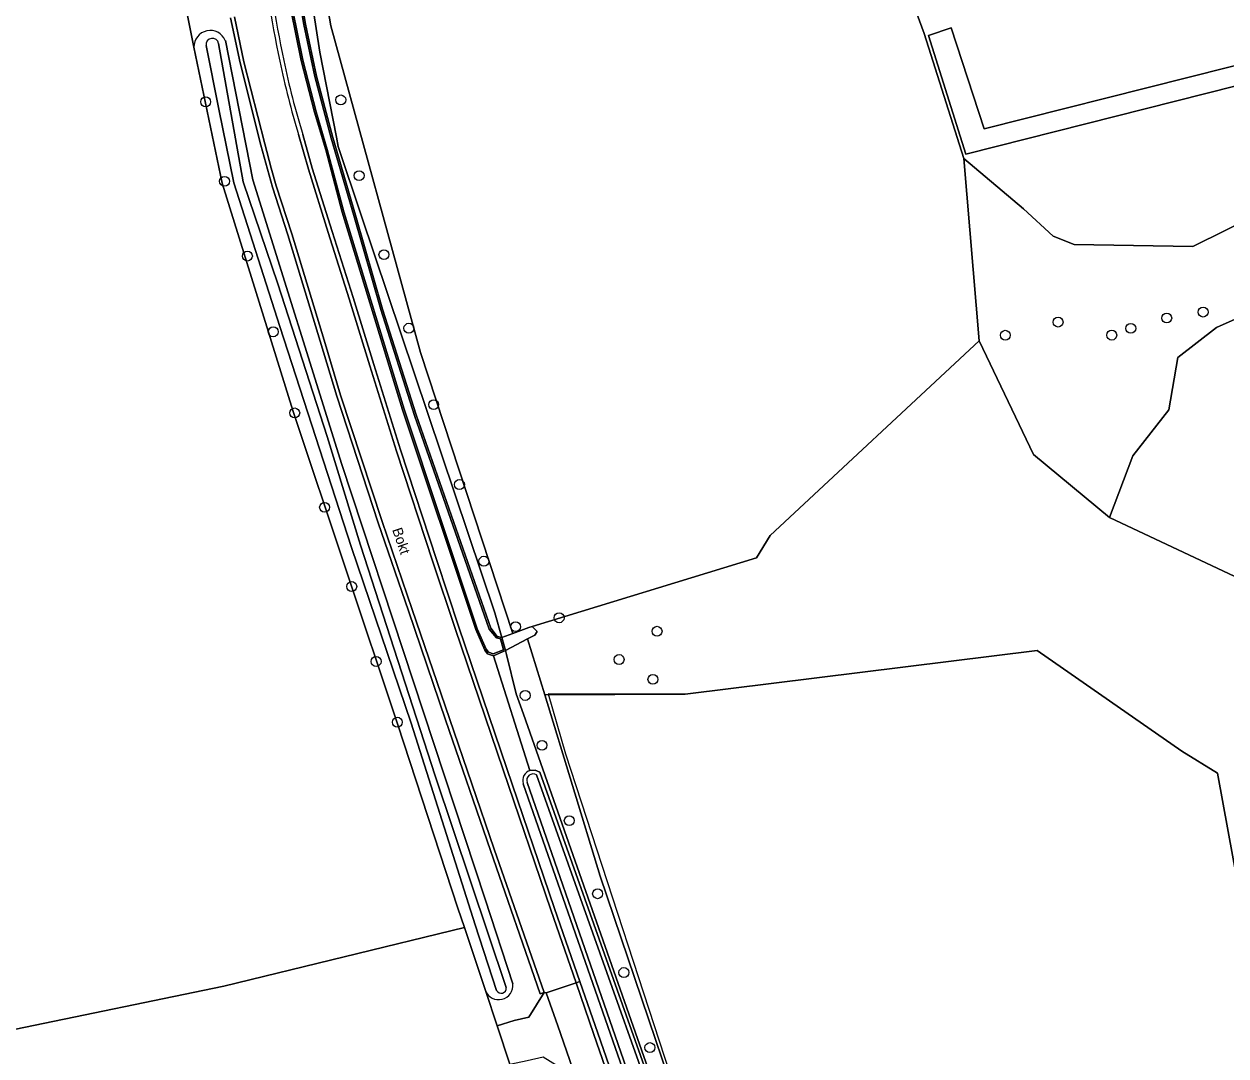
# Model space of a CAD drawing. Extents: x 162510 to 163918, y 388494 to 389774.
# Drawn here: x 163242.1 to 163360.7, y 389132.9 to 389234.8 of the extents above; entities that cross this region are included whole.
import ezdxf

# ---------------------------------------------------------------- set-up
doc = ezdxf.new("R2010")
doc.units = 0
for name, color, linetype in [('IMGEO_Boom', 7, 'Continuous'), ('IMGEO_Duiker', 7, 'Continuous'), ('IMGEO_Erf', 7, 'Continuous'), ('IMGEO_Grasland_agrarisch', 7, 'Continuous'), ('IMGEO_Grasland_overig', 7, 'Continuous'), ('IMGEO_Groenvoorziening', 7, 'Continuous'), ('IMGEO_Hek', 7, 'Continuous'), ('IMGEO_Loofbos', 7, 'Continuous'), ('IMGEO_Oever', 7, 'Continuous'), ('IMGEO_Openbare_ruimte_label', 7, 'Continuous'), ('IMGEO_Rijbaan_lokaal_gesloten', 7, 'Continuous'), ('IMGEO_Rijbaan_lokaal_halfverhard', 7, 'Continuous'), ('IMGEO_Rijbaan_lokaal_open', 7, 'Continuous'), ('IMGEO_Waterloop', 7, 'Continuous')]:
    doc.layers.add(name, color=color, linetype=linetype)

msp = doc.modelspace()

# ---------------------------------------------------------------- linework, layer by layer
at = {"layer": 'IMGEO_Boom'}
for centre in [(163260, 389227.15), (163273.34, 389227.34), (163261.86, 389219.3), (163275.15, 389219.86), (163277.6, 389212.06), (163264.12, 389211.92), (163358.49, 389206.39), (163344.17, 389205.4), (163354.9, 389205.8), (163266.67, 389204.44), (163280.06, 389204.8), (163338.96, 389204.1), (163349.47, 389204.11), (163351.35, 389204.78), (163282.51, 389197.25), (163268.79, 389196.43), (163285.06, 389189.36), (163271.74, 389187.11), (163287.47, 389181.79), (163274.42, 389179.29), (163290.6, 389175.32), (163294.9, 389176.2), (163304.57, 389174.87), (163276.83, 389171.89), (163300.82, 389172.08), (163304.16, 389170.12), (163291.55, 389168.53), (163278.92, 389165.89), (163293.21, 389163.61), (163295.9, 389156.17), (163298.7, 389148.95), (163301.29, 389141.17), (163303.86, 389133.76)]:
    msp.add_circle(centre, 0.489, dxfattribs=at)
at = {"layer": 'IMGEO_Duiker'}
msp.add_lwpolyline([(163288.41, 389172.46), (163292.02, 389161.13)], dxfattribs=at)
at = {"layer": 'IMGEO_Erf'}
msp.add_lwpolyline([(163295.99, 389113.82), (163290.94, 389129.38), (163290.9, 389129.51), (163290.03, 389132.12), (163288.77, 389135.91), (163287.62, 389139.39), (163285.54, 389145.63), (163261.78, 389139.83), (163241.1, 389135.56), (163217.2, 389130.56), (163224.26, 389085.9), (163224.4, 389084.98), (163231.97, 389086.77), (163247.9, 389090.8), (163281.65, 389099.34), (163299.1, 389104.33), (163298.18, 389106.71), (163299.75, 389107.17), (163299.51, 389107.92), (163299.36, 389108.41), (163297.84, 389113.03)], dxfattribs=at)
at = {"layer": 'IMGEO_Grasland_agrarisch'}
for points in [[(163388.88, 389260.58), (163349.51, 389250), (163329.29, 389244.57), (163327.23, 389244.02), (163330.95, 389233.91), (163334.85, 389221.56), (163340.75, 389216.59), (163343.69, 389213.89), (163345.77, 389213.07), (163357.46, 389212.88), (163363.99, 389216.09)], [(163241.1, 389135.56), (163261.78, 389139.83), (163285.54, 389145.63), (163284.91, 389147.53), (163278.98, 389165.63), (163268.64, 389196.56), (163261.63, 389219.11), (163258.84, 389232.54), (163257.29, 389240.35), (163255.91, 389250.62), (163255.18, 389257.46), (163254.95, 389259.65), (163234.72, 389258.87)], [(163446.97, 389250.33), (163429.34, 389245.86), (163417.88, 389242.96), (163335.07, 389221.97), (163331.37, 389233.7), (163333.61, 389234.45), (163336.86, 389224.47), (163417.3, 389244.79), (163428.76, 389247.68), (163436.64, 389249.67), (163454.78, 389254.26)], [(163367.57, 389208.33), (163359.8, 389204.88), (163355.99, 389201.92), (163355.12, 389196.75), (163351.55, 389192.19), (163349.24, 389186.12), (163364.42, 389178.96)]]:
    msp.add_lwpolyline(points, dxfattribs=at)
for points in [[(163290.32, 389174.65), (163291.92, 389175.23), (163292.25, 389175.35), (163314.39, 389182.12), (163315.73, 389184.32), (163336.37, 389203.54), (163334.85, 389221.56), (163330.95, 389233.91), (163327.23, 389244.02), (163327.18, 389244), (163326.31, 389243.96), (163324.51, 389250), (163323.9, 389252.04), (163322.98, 389255.13), (163320.23, 389256.1), (163270.63, 389254.09), (163271.19, 389241.33), (163272.35, 389234.67), (163281.2, 389202.41)], [(163307.16, 389126.5), (163310.88, 389115.86), (163314.09, 389104.33), (163316.99, 389092.13), (163318.51, 389073.31), (163367.52, 389078.3), (163374.79, 389079.28), (163366.65, 389123.96), (163359.92, 389160.85), (163356.4, 389163.04), (163342.1, 389172.97), (163307.36, 389168.67), (163293.48, 389168.59), (163298.96, 389150.69)], [(163359.92, 389160.85), (163356.4, 389163.04), (163342.1, 389172.97), (163307.36, 389168.67), (163293.81, 389168.69), (163295.53, 389162.77), (163307.35, 389126.56), (163307.16, 389126.5), (163310.88, 389115.86), (163314.09, 389104.33), (163316.99, 389092.13), (163318.51, 389073.31), (163367.52, 389078.3), (163374.79, 389079.28), (163366.65, 389123.96)]]:
    msp.add_lwpolyline(points, close=True, dxfattribs=at)
at = {"layer": 'IMGEO_Grasland_overig'}
for points in [[(163259.08, 389250.92), (163259.64, 389245.33), (163260.33, 389240.89), (163259.65, 389240.76), (163259.1, 389240.51), (163258.43, 389240.54), (163257.29, 389240.35), (163258.84, 389232.54)], [(163269.01, 389239.92), (163269.85, 389234.81), (163270.95, 389229.7), (163272.54, 389223.62), (163274.79, 389215.95), (163277.45, 389206.69), (163280.78, 389196.25), (163288.14, 389175.16), (163288.79, 389174.36), (163289.23, 389174.26), (163288.55, 389176.68), (163275.36, 389215.95), (163273.08, 389222.75), (163272.9, 389223.65), (163271.28, 389232.05), (163270.01, 389240.16)], [(163292.02, 389161.13), (163288.41, 389172.46), (163287.83, 389172.65), (163287.56, 389173), (163286.66, 389175.04), (163279.44, 389196.74), (163273.49, 389216.24), (163271.85, 389222.4), (163270.74, 389226.12), (163269.44, 389231.24), (163268.41, 389236.27)], [(163280.01, 389176.89), (163277.03, 389185.58), (163272.94, 389198.07), (163271.3, 389203.51), (163268.11, 389214.02), (163266.58, 389218.73), (163266.09, 389220.5), (163265.44, 389222.88), (163263.39, 389230.99), (163262.46, 389235.46)], [(163261.94, 389233.21), (163264.65, 389219.44), (163273.43, 389191.33), (163287.58, 389148.42), (163290.32, 389140.06)], [(163269.59, 389223.92), (163270.52, 389220.61), (163272.48, 389214.36), (163274.56, 389207.83), (163276.6, 389201.21), (163279.23, 389192.78), (163282.82, 389181.85), (163285.01, 389175.27), (163289.74, 389161.32), (163294.44, 389147.5), (163296.94, 389140.29), (163298.71, 389135.19), (163302.63, 389123.88), (163306.31, 389112.91), (163307.37, 389109.75), (163307.92, 389107.81), (163308.74, 389104.91), (163309.77, 389101.2)], [(163287.62, 389139.39), (163288.77, 389135.91), (163290.45, 389136.42), (163291.92, 389136.77), (163293.42, 389139.21), (163293.04, 389139.08), (163288.11, 389153.21), (163283.68, 389166.12), (163280.01, 389176.89)], [(163380.6, 389076.41), (163382.81, 389076.72), (163383.64, 389076.96), (163385.39, 389077.66), (163386.69, 389078.32), (163386.48, 389080.86), (163374.79, 389079.28), (163367.52, 389078.3), (163318.51, 389073.31), (163316.99, 389092.13), (163314.09, 389104.33), (163310.88, 389115.86), (163307.16, 389126.5), (163298.96, 389150.69), (163293.48, 389168.59), (163291.79, 389174.11), (163289.6, 389172.96)], [(163289.6, 389172.96), (163289.7, 389172.58), (163290.67, 389168.7), (163291.38, 389166.69), (163307.93, 389119.58), (163308.65, 389118.16), (163310.82, 389111.46), (163312.33, 389106.03), (163313.79, 389100.58), (163315.67, 389092.46), (163317.15, 389071.29), (163317.16, 389071.04), (163328.39, 389071.63), (163350.59, 389073.13), (163366.02, 389074.66), (163372.1, 389075.6), (163375.23, 389076.38), (163378.48, 389077.44), (163380.72, 389078.49), (163381.48, 389078.62), (163381.77, 389078.52), (163381.92, 389078.25), (163381.86, 389077.89)], [(163306.08, 389117.55), (163291.36, 389159.82)]]:
    msp.add_lwpolyline(points, dxfattribs=at)
msp.add_lwpolyline([(163336.37, 389203.54), (163341.73, 389192.33), (163349.24, 389186.12), (163351.55, 389192.19), (163355.12, 389196.75), (163355.99, 389201.92), (163359.8, 389204.88), (163367.57, 389208.33), (163374.84, 389208.08), (163378.41, 389205.74), (163383.96, 389207.59), (163391.85, 389211.28), (163392.71, 389214.73), (163390.37, 389218.92), (163383.1, 389221.75), (163377.8, 389223.11), (163371.51, 389220.89), (163363.99, 389216.09), (163357.46, 389212.88), (163345.77, 389213.07), (163343.69, 389213.89), (163340.75, 389216.59), (163334.85, 389221.56)], close=True, dxfattribs=at)
for centre, radius, start, end in [((163384.64, 389256.15), 119.55, 185.9996, 192.0239), ((163260.45, 389232.59), 1.61, 22.4064, 182.0203), ((163344.2, 389246.9), 78.07, 191.5701, 197.12), ((163292.34, 389160.15), 1.03, 107.8328, 198.5842), ((163288.93, 389139.89), 1.4, 201.2048, 6.7579)]:
    msp.add_arc(centre, radius, start, end, dxfattribs=at)
at = {"layer": 'IMGEO_Groenvoorziening'}
for points in [[(163288.55, 389176.68), (163289.23, 389174.26), (163290.32, 389174.65), (163281.2, 389202.41), (163272.35, 389234.67), (163271.19, 389241.33), (163270.63, 389254.09), (163269.08, 389254.14), (163268.99, 389251.22), (163269.1, 389250), (163270.01, 389240.16), (163271.28, 389232.05), (163272.9, 389223.65), (163273.08, 389222.75), (163275.36, 389215.95)], [(163289.6, 389172.96), (163288.41, 389172.46), (163292.02, 389161.13), (163292.52, 389161.17), (163292.98, 389160.96), (163310.56, 389111.5), (163312.21, 389105.99), (163312.33, 389106.03), (163310.82, 389111.46), (163308.65, 389118.16), (163307.93, 389119.58), (163291.38, 389166.69), (163290.67, 389168.7), (163289.7, 389172.58)]]:
    msp.add_lwpolyline(points, close=True, dxfattribs=at)
at = {"layer": 'IMGEO_Hek'}
msp.add_lwpolyline([(163291.79, 389174.11), (163293.48, 389168.59), (163298.96, 389150.69), (163307.16, 389126.5)], dxfattribs=at)
at = {"layer": 'IMGEO_Loofbos'}
msp.add_lwpolyline([(163364.42, 389178.96), (163349.24, 389186.12), (163341.73, 389192.33), (163336.37, 389203.54), (163315.73, 389184.32), (163314.39, 389182.12), (163292.25, 389175.35), (163292.73, 389174.84), (163292.5, 389174.48), (163292.18, 389174.32), (163291.79, 389174.11), (163293.48, 389168.59), (163307.36, 389168.67), (163342.1, 389172.97), (163356.4, 389163.04), (163359.92, 389160.85), (163366.65, 389123.96)], dxfattribs=at)
at = {"layer": 'IMGEO_Oever'}
for points in [[(163268.41, 389236.27), (163269.44, 389231.24), (163270.74, 389226.12), (163271.85, 389222.4), (163273.49, 389216.24), (163279.44, 389196.74), (163286.66, 389175.04), (163287.56, 389173), (163287.83, 389172.65), (163288.41, 389172.46), (163289.6, 389172.96), (163289.23, 389174.26), (163288.79, 389174.36), (163288.14, 389175.16), (163280.78, 389196.25), (163277.45, 389206.69), (163274.79, 389215.95), (163272.54, 389223.62), (163270.95, 389229.7), (163269.85, 389234.81), (163269.01, 389239.92)], [(163268.84, 389239.9), (163269.69, 389234.78), (163270.79, 389229.66), (163272.38, 389223.57), (163274.63, 389215.91), (163277.29, 389206.64), (163280.62, 389196.19), (163287.99, 389175.07), (163288.7, 389174.22), (163289.1, 389174.12), (163289.4, 389173.05), (163288.4, 389172.64), (163287.93, 389172.79), (163287.7, 389173.09), (163286.82, 389175.1), (163279.6, 389196.79), (163273.65, 389216.29), (163272.01, 389222.45), (163270.9, 389226.16), (163269.6, 389231.27), (163268.58, 389236.3)], [(163280.3, 389165.8), (163274.39, 389183.15), (163267.32, 389204.95), (163262.78, 389219.16), (163261.29, 389226.41), (163260.05, 389232.7)], [(163261.27, 389232.91), (163263.69, 389219.26), (163267.13, 389209.19), (163272, 389194.09), (163275.3, 389183.38), (163282.67, 389160.59), (163289.68, 389139.68)], [(163290.32, 389140.06), (163287.58, 389148.42), (163273.43, 389191.33), (163264.65, 389219.44), (163261.94, 389233.21)], [(163258.84, 389232.54), (163261.63, 389219.11), (163268.64, 389196.56), (163278.98, 389165.63), (163284.91, 389147.53), (163285.54, 389145.63), (163287.62, 389139.39)], [(163288.73, 389139.41), (163286.62, 389145.89), (163280.3, 389165.8)], [(163292.98, 389160.96), (163292.52, 389161.17), (163292.02, 389161.13)], [(163292.67, 389160.68), (163310.2, 389111.38), (163311.83, 389105.89)], [(163312.21, 389105.99), (163310.56, 389111.5), (163292.98, 389160.96)], [(163291.36, 389159.82), (163306.08, 389117.55)], [(163306.44, 389117.67), (163291.73, 389159.93)]]:
    msp.add_lwpolyline(points, dxfattribs=at)
for centre, radius, start, end in [((163260.45, 389232.59), 1.61, 22.4064, 182.0203), ((163260.66, 389232.8), 0.623, 10.2286, 188.7112), ((163292.34, 389160.15), 1.03, 107.8328, 198.5842), ((163292.33, 389160.15), 0.632, 57.1299, 199.9955), ((163288.93, 389139.89), 1.4, 201.2048, 6.7579), ((163289.18, 389139.62), 0.501, 205.7041, 6.4733)]:
    msp.add_arc(centre, radius, start, end, dxfattribs=at)
at = {"layer": 'IMGEO_Rijbaan_lokaal_gesloten'}
for points in [[(163262.86, 389235.54), (163263.78, 389231.09), (163265.83, 389222.99), (163266.48, 389220.61), (163266.96, 389218.85), (163268.49, 389214.13), (163271.69, 389203.62), (163273.32, 389198.2), (163277.41, 389185.71), (163280.39, 389177.02), (163284.06, 389166.25), (163288.49, 389153.34), (163293.42, 389139.21), (163293.61, 389139.17), (163293.62, 389139.16), (163293.62, 389139.16), (163296.57, 389140.16), (163294.07, 389147.37), (163289.36, 389161.2), (163284.64, 389175.15), (163282.44, 389181.73), (163278.85, 389192.65), (163276.21, 389201.09), (163274.17, 389207.71), (163272.1, 389214.24)], [(163272.1, 389214.24), (163270.14, 389220.49), (163269.17, 389223.93)], [(163309.38, 389101.1), (163308.36, 389104.8), (163307.53, 389107.7), (163306.99, 389109.63), (163305.93, 389112.78), (163302.25, 389123.75), (163298.33, 389135.05), (163296.57, 389140.16), (163293.62, 389139.16), (163293.62, 389139.16), (163294.76, 389135.9), (163296.51, 389130.87), (163296.4, 389130.64), (163297.11, 389128.39), (163299.6, 389120.88), (163301.08, 389116.56), (163303.34, 389109.77), (163304.84, 389104.83)]]:
    msp.add_lwpolyline(points, dxfattribs=at)
for centre, radius, start, end in [((163384.99, 389256.21), 120.31, 186.0093, 192.0139), ((163342.75, 389246.57), 76.98, 191.5428, 197.0994)]:
    msp.add_arc(centre, radius, start, end, dxfattribs=at)
at = {"layer": 'IMGEO_Rijbaan_lokaal_halfverhard'}
for points in [[(163262.46, 389235.46), (163263.39, 389230.99), (163265.44, 389222.88), (163266.09, 389220.5), (163266.58, 389218.73), (163268.11, 389214.02), (163271.3, 389203.51), (163272.94, 389198.07), (163277.03, 389185.58), (163280.01, 389176.89), (163283.68, 389166.12), (163288.11, 389153.21), (163293.04, 389139.08), (163293.42, 389139.21), (163288.49, 389153.34), (163284.06, 389166.25), (163280.39, 389177.02), (163277.41, 389185.71), (163273.32, 389198.2), (163271.69, 389203.62), (163268.49, 389214.13), (163266.96, 389218.85), (163266.48, 389220.61), (163265.83, 389222.99), (163263.78, 389231.09), (163262.86, 389235.54)], [(163269.17, 389223.93), (163270.14, 389220.49), (163272.1, 389214.24), (163274.17, 389207.71), (163276.21, 389201.09), (163278.85, 389192.65), (163282.44, 389181.73), (163284.64, 389175.15), (163289.36, 389161.2), (163294.07, 389147.37), (163296.57, 389140.16), (163296.94, 389140.29), (163294.44, 389147.5), (163289.74, 389161.32), (163285.01, 389175.27), (163282.82, 389181.85), (163279.23, 389192.78), (163276.6, 389201.21), (163274.56, 389207.83), (163272.48, 389214.36), (163270.52, 389220.61), (163269.59, 389223.92)], [(163296.94, 389140.29), (163296.57, 389140.16), (163298.33, 389135.05), (163302.25, 389123.75), (163305.93, 389112.78), (163306.99, 389109.63), (163307.53, 389107.7), (163308.36, 389104.8), (163309.38, 389101.1)], [(163309.77, 389101.2), (163308.74, 389104.91), (163307.92, 389107.81), (163307.37, 389109.75), (163306.31, 389112.91), (163302.63, 389123.88), (163298.71, 389135.19), (163296.94, 389140.29)]]:
    msp.add_lwpolyline(points, dxfattribs=at)
for centre, radius, start, end in [((163384.99, 389256.21), 120.31, 186.0093, 192.0139), ((163384.64, 389256.15), 119.55, 185.9996, 192.0239), ((163342.75, 389246.57), 76.98, 191.5428, 197.0994), ((163344.2, 389246.9), 78.07, 191.5701, 197.12)]:
    msp.add_arc(centre, radius, start, end, dxfattribs=at)
at = {"layer": 'IMGEO_Rijbaan_lokaal_open'}
msp.add_lwpolyline([(163293.62, 389139.16), (163293.61, 389139.17), (163293.42, 389139.21), (163291.92, 389136.77), (163290.45, 389136.42), (163288.77, 389135.91), (163290.03, 389132.12), (163291.73, 389132.49), (163293.32, 389132.86), (163296.51, 389130.87), (163294.76, 389135.9)], close=True, dxfattribs=at)
at = {"layer": 'IMGEO_Waterloop'}
for points in [[(163454.78, 389254.26), (163436.64, 389249.67), (163428.76, 389247.68), (163417.3, 389244.79), (163336.86, 389224.47), (163333.61, 389234.45), (163331.37, 389233.7), (163335.07, 389221.97), (163417.88, 389242.96), (163429.34, 389245.86), (163446.97, 389250.33), (163455.21, 389252.41), (163499.92, 389263.74), (163524.26, 389269.9), (163523.7, 389271.7), (163500.08, 389265.73)], [(163289.6, 389172.96), (163291.79, 389174.11), (163292.18, 389174.32), (163292.5, 389174.48), (163292.73, 389174.84), (163292.25, 389175.35), (163291.92, 389175.23), (163290.32, 389174.65), (163289.23, 389174.26)]]:
    msp.add_lwpolyline(points, close=True, dxfattribs=at)
for points in [[(163268.58, 389236.3), (163269.6, 389231.27), (163270.9, 389226.16), (163272.01, 389222.45), (163273.65, 389216.29), (163279.6, 389196.79), (163286.82, 389175.1), (163287.7, 389173.09), (163287.93, 389172.79), (163288.4, 389172.64), (163289.4, 389173.05), (163289.1, 389174.12), (163288.7, 389174.22), (163287.99, 389175.07), (163280.62, 389196.19), (163277.29, 389206.64), (163274.63, 389215.91), (163272.38, 389223.57), (163270.79, 389229.66), (163269.69, 389234.78), (163268.84, 389239.9)], [(163260.05, 389232.7), (163261.29, 389226.41), (163262.78, 389219.16), (163267.32, 389204.95), (163274.39, 389183.15), (163280.3, 389165.8), (163286.62, 389145.89), (163288.73, 389139.41)], [(163272, 389194.09), (163267.13, 389209.19), (163263.69, 389219.26), (163261.27, 389232.91)], [(163289.68, 389139.68), (163282.67, 389160.59), (163275.3, 389183.38), (163272, 389194.09)], [(163311.83, 389105.89), (163310.2, 389111.38), (163292.67, 389160.68)], [(163291.73, 389159.93), (163306.44, 389117.67)]]:
    msp.add_lwpolyline(points, dxfattribs=at)
for centre, radius, start, end in [((163260.66, 389232.8), 0.623, 10.2286, 188.7112), ((163292.33, 389160.15), 0.632, 57.1299, 199.9955), ((163289.18, 389139.62), 0.501, 205.7041, 6.4733)]:
    msp.add_arc(centre, radius, start, end, dxfattribs=at)

# ---------------------------------------------------------------- texts
at = {"layer": 'IMGEO_Openbare_ruimte_label'}
msp.add_text('Bokt', height=1, rotation=288.8518, dxfattribs=at).set_placement((163278.4, 389184.9))

doc.saveas('drawing.dxf')
